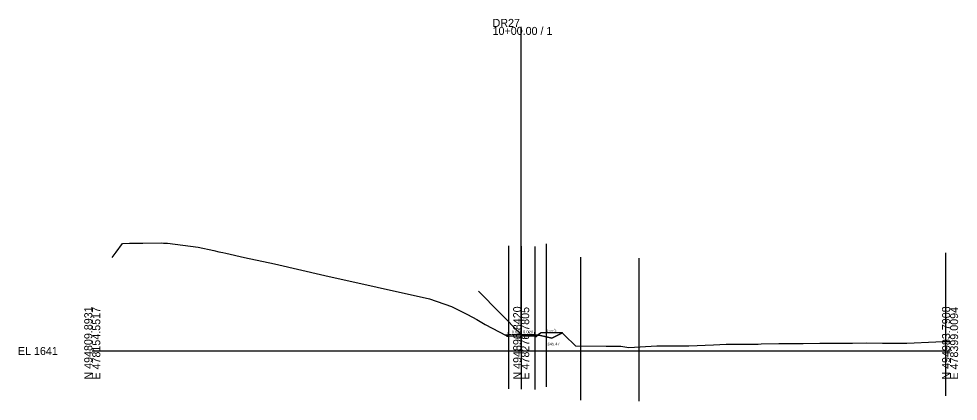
# Model space of a CAD drawing. Extents: x -26 to 478410, y -18 to 495058.
# Drawn here: x 1274.3 to 1602.8, y 482.4 to 616.2 of the extents above; entities that cross this region are included whole.
import ezdxf

# ---------------------------------------------------------------- set-up
doc = ezdxf.new("R2010")
doc.units = 0
for name, color, linetype in [('Exist Cross Section Cell', 7, 'Continuous'), ('Exist XS Center Line Elevation Label', 7, 'Continuous'), ('Exist XS Ground Line', 7, 'Continuous'), ('Prop XS Ditch Slope Text', 7, 'Continuous'), ('Prop XS Ditch Standard Text', 7, 'Continuous'), ('Prop XS Dump Level', 7, 'Continuous'), ('Prop XS Earthwork Shape', 7, 'Continuous'), ('Prop XS EOT Tick Mark', 7, 'Continuous'), ('Prop XS Finish Grade', 7, 'Continuous'), ('Prop XS Finish Grade Earthwork', 7, 'Continuous'), ('Prop XS Finish Grade Pavement', 7, 'Continuous'), ('Prop XS Pvmt Edge Slope', 7, 'Continuous'), ('Prop XS SE Text', 7, 'Continuous'), ('Prop XS Shoulder Borrow Shape', 7, 'Continuous'), ('Prop XS Side Slope Text', 7, 'Continuous'), ('Prop XS Subgrade Earthwork', 7, 'Continuous'), ('Scratch_Level_4', 7, 'Continuous'), ('Scratch_Level_5', 7, 'Continuous')]:
    doc.layers.add(name, color=color, linetype=linetype)

msp = doc.modelspace()

# ---------------------------------------------------------------- linework, layer by layer
at = {"layer": 'Exist Cross Section Cell'}
for p, q in [((1450, 500), (1450, 613.37)), ((1300, 500), (1450, 500)), ((1450, 500), (1600, 500))]:
    msp.add_line(p, q, dxfattribs=at)
at = {"layer": 'Exist XS Ground Line'}
msp.add_lwpolyline([(1306.94, 532.75), (1308.32, 534.61), (1310.53, 537.6), (1313.03, 537.7), (1317.71, 537.68), (1324.29, 537.79), (1324.88, 537.77), (1325.3, 537.77), (1326.31, 537.67), (1337.03, 536.37), (1342.48, 535.1), (1344.27, 534.74), (1345.62, 534.44), (1346.67, 534.22), (1353.19, 532.76), (1363.69, 530.54), (1381.3, 526.41), (1417.96, 518.27), (1425.64, 515.59), (1431.28, 512.73), (1434.52, 510.98), (1437.37, 509.3), (1444.78, 505.44), (1445.62, 505.82), (1446.44, 505.79), (1450, 505.69), (1454.78, 505.56), (1455.3, 505.35), (1456.39, 506.11), (1456.98, 506.45), (1463.77, 506.49), (1464.23, 506.5), (1465.11, 505.52), (1469.05, 501.83), (1479.78, 501.7), (1482.67, 501.65), (1484.87, 501.64), (1487.68, 501.25), (1497.47, 501.76), (1502.39, 501.82), (1508.69, 501.82), (1517.29, 502.21), (1521.69, 502.35), (1525.7, 502.37), (1531.35, 502.43), (1532.88, 502.44), (1533.97, 502.46), (1540.05, 502.59), (1546.24, 502.66), (1547.22, 502.66), (1548.6, 502.67), (1554.39, 502.7), (1558.51, 502.7), (1561.57, 502.71), (1565.86, 502.76), (1570.79, 502.83), (1576.32, 502.78), (1584.85, 502.76), (1595.04, 503.19), (1597.43, 503.3), (1600, 503.34)], dxfattribs=at)
at = {"layer": 'Prop XS Dump Level'}
for p, q in [((1450, 505.72), (1446.86, 505.66)), ((1454.75, 505.63), (1450, 505.72))]:
    msp.add_line(p, q, dxfattribs=at)
at = {"layer": 'Prop XS Earthwork Shape'}
msp.add_lwpolyline([(1444.64, 505.51), (1444.78, 505.44), (1445.62, 505.82), (1446.44, 505.79), (1450, 505.69), (1454.78, 505.56), (1455.3, 505.35), (1456.39, 506.11), (1456.98, 506.45), (1463.77, 506.49), (1464.23, 506.5), (1464.41, 506.3), (1460.75, 504.47), (1456.75, 505.47), (1455.78, 505.54), (1455.31, 505.07), (1454.75, 505.08), (1450, 505.18), (1445.62, 505.09), (1445.07, 505.08)], close=True, dxfattribs=at)
at = {"layer": 'Prop XS EOT Tick Mark'}
for p, q in [((1445.62, 505.63), (1445.62, 506.63)), ((1454.75, 505.63), (1454.75, 506.63))]:
    msp.add_line(p, q, dxfattribs=at)
at = {"layer": 'Prop XS Finish Grade'}
for p, q in [((1445.62, 505.63), (1444.6, 505.55)), ((1454.75, 505.63), (1455.78, 505.54))]:
    msp.add_line(p, q, dxfattribs=at)
at = {"layer": 'Prop XS Finish Grade Earthwork'}
for p, q in [((1460.75, 504.47), (1464.41, 506.3)), ((1444.6, 505.55), (1444.57, 505.55)), ((1455.78, 505.54), (1456.75, 505.47)), ((1456.75, 505.47), (1460.75, 504.47))]:
    msp.add_line(p, q, dxfattribs=at)
at = {"layer": 'Prop XS Finish Grade Pavement'}
for p, q in [((1445.62, 505.63), (1450, 505.72)), ((1450, 505.72), (1454.75, 505.63))]:
    msp.add_line(p, q, dxfattribs=at)
at = {"layer": 'Prop XS Pvmt Edge Slope'}
for p, q in [((1445.62, 505.63), (1445.07, 505.08)), ((1454.75, 505.63), (1455.31, 505.07))]:
    msp.add_line(p, q, dxfattribs=at)
at = {"layer": 'Prop XS Shoulder Borrow Shape'}
for points in [[(1445.62, 505.63), (1445.07, 505.08), (1444.6, 505.55)], [(1455.31, 505.07), (1455.78, 505.54), (1454.75, 505.63)]]:
    msp.add_lwpolyline(points, close=True, dxfattribs=at)
at = {"layer": 'Prop XS Subgrade Earthwork'}
for p, q in [((1445.07, 505.08), (1444.6, 505.55)), ((1445.62, 505.09), (1445.07, 505.08)), ((1450, 505.18), (1445.62, 505.09)), ((1454.75, 505.08), (1450, 505.18)), ((1454.75, 505.08), (1455.31, 505.07)), ((1455.31, 505.07), (1455.78, 505.54))]:
    msp.add_line(p, q, dxfattribs=at)
at = {"layer": 'Scratch_Level_4'}
for p, q in [((1445.62, 536.82), (1445.62, 486.82)), ((1450, 536.69), (1450, 486.69)), ((1454.78, 536.56), (1454.78, 486.56)), ((1458.75, 537.46), (1458.75, 487.46)), ((1470.71, 532.81), (1470.71, 482.81)), ((1491.2, 532.43), (1491.2, 482.43)), ((1598.43, 534.31), (1598.43, 484.31))]:
    msp.add_line(p, q, dxfattribs=at)
at = {"layer": 'Scratch_Level_5'}
msp.add_line((1450, 505.72), (1435.05, 520.95), dxfattribs=at)

# ---------------------------------------------------------------- texts
at = {"layer": 'Exist Cross Section Cell'}
for s, p in [('DR27', (1440, 613.37)), ('10+00.00 / 1', (1440, 610.57)), ('EL 1641', (1274, 498.6))]:
    msp.add_text(s, height=2.8, dxfattribs=at).set_placement(p)
for s, p in [('N 494809.8931', (1300, 490)), ('E 478154.5517', (1302.8, 490)), ('N 494896.8420', (1450, 490)), ('E 478276.7805', (1452.8, 490)), ('N 494983.7908', (1600, 490)), ('E 478399.0094', (1602.8, 490))]:
    msp.add_text(s, height=2.8, rotation=90, dxfattribs=at).set_placement(p)
at = {"layer": 'Exist XS Center Line Elevation Label'}
msp.add_text('1646.69', height=0.75, dxfattribs=at).set_placement((1448.29, 504.15))
at = {"layer": 'Prop XS Ditch Slope Text'}
msp.add_text('4:1', height=1, rotation=345.965, dxfattribs=at).set_placement((1458.43, 506.59))
at = {"layer": 'Prop XS Ditch Standard Text'}
msp.add_text('1645.47', height=1, dxfattribs=at).set_placement((1458.47, 501.97))
at = {"layer": 'Prop XS Dump Level'}
for p in [(1443.62, 505.43), (1456.75, 505.43)]:
    msp.add_text('Case1', height=0.04, dxfattribs=at).set_placement(p)
at = {"layer": 'Prop XS SE Text'}
for rotation, p in [(1.1458, (1446.7, 506.15)), (358.8542, (1450.65, 506.21))]:
    msp.add_text('0.020', height=1, rotation=rotation, dxfattribs=at).set_placement(p)
at = {"layer": 'Prop XS Side Slope Text'}
msp.add_text('2:1', height=1, rotation=26.563, dxfattribs=at).set_placement((1460.79, 506.16))

doc.saveas('drawing.dxf')
